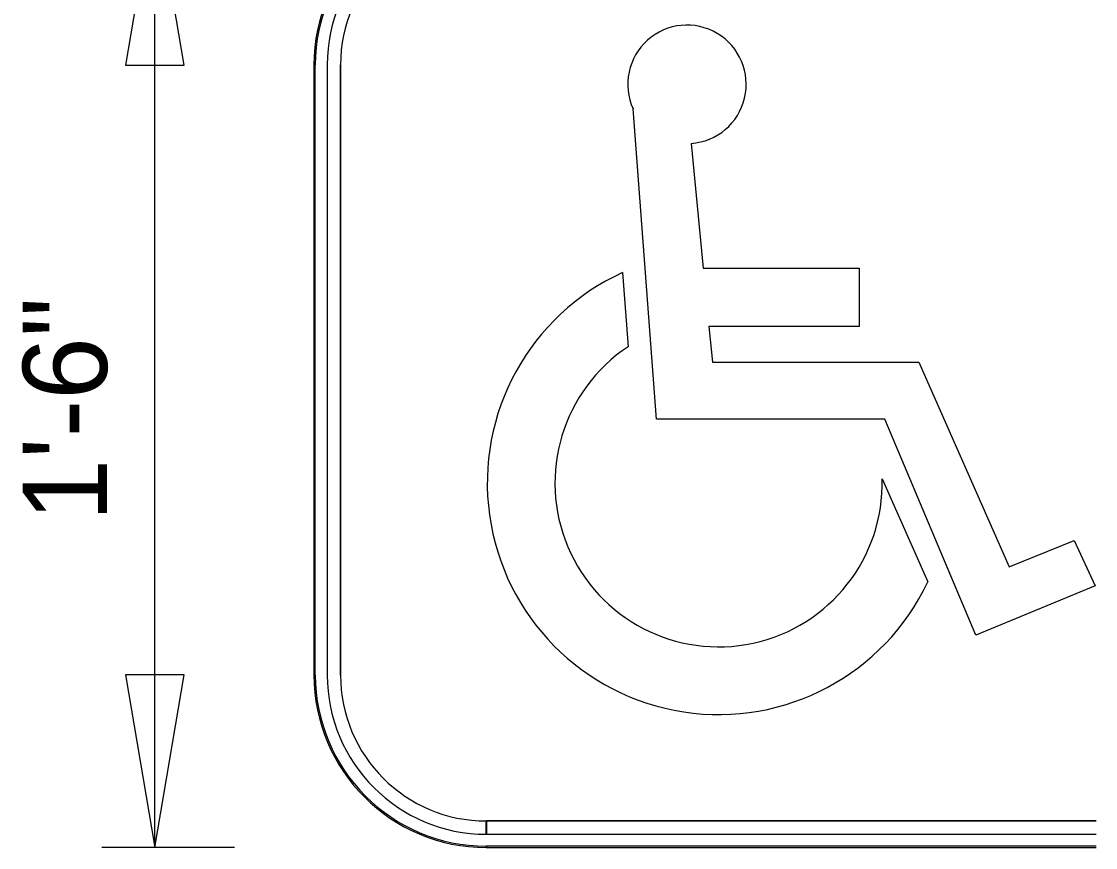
# Model space of a CAD drawing. Extents: x 0 to 770, y 0 to 495.
# Drawn here: x 488.58 to 533.2, y 427.82 to 462.11 of the extents above; entities that cross this region are included whole.
import ezdxf

# ---------------------------------------------------------------- set-up
doc = ezdxf.new("R2010")
doc.units = 0
for name, color, linetype in [('Default', 7, 'Continuous'), ('Dimension', 7, 'Continuous'), ('GSBWFill', 7, 'Continuous'), ('GSColorFill', 7, 'Continuous'), ('GSDims', 7, 'Continuous'), ('GSOutline', 7, 'Continuous'), ('TextStructures', 7, 'Continuous')]:
    doc.layers.add(name, color=color, linetype=linetype)

msp = doc.modelspace()

# ---------------------------------------------------------------- linework, layer by layer
at = {"layer": 'Default'}
for p, q in [((513.555, 451.692), (513.785, 448.609)), ((513.555, 451.692), (513.555, 451.692)), ((513.555, 451.692), (513.785, 448.609)), ((513.555, 451.692), (513.555, 451.692)), ((513.555, 451.692), (513.785, 448.609)), ((513.555, 451.692), (513.555, 451.692)), ((524.338, 443.123), (526.233, 438.843)), ((524.338, 443.123), (526.233, 438.843)), ((524.338, 443.123), (526.233, 438.843))]:
    msp.add_line(p, q, dxfattribs=at)
for points in [[(528.232, 436.629), (524.444, 445.595), (514.968, 445.595), (513.989, 458.487)], [(528.232, 436.629), (524.444, 445.595), (514.968, 445.595), (513.989, 458.487)], [(528.232, 436.629), (524.444, 445.595), (514.968, 445.595), (513.989, 458.487)], [(516.403, 457.05), (516.905, 451.874), (523.379, 451.874), (523.379, 449.449), (517.139, 449.449), (517.287, 447.975), (525.865, 447.975), (529.611, 439.473), (532.312, 440.561), (533.19, 438.681), (528.232, 436.629)], [(516.403, 457.05), (516.905, 451.874), (523.379, 451.874), (523.379, 449.449), (517.139, 449.449), (517.287, 447.975), (525.865, 447.975), (529.611, 439.473), (532.312, 440.561), (533.19, 438.681), (528.232, 436.629)], [(516.403, 457.05), (516.905, 451.874), (523.379, 451.874), (523.379, 449.449), (517.139, 449.449), (517.287, 447.975), (525.865, 447.975), (529.611, 439.473), (532.312, 440.561), (533.19, 438.681), (528.232, 436.629)]]:
    msp.add_lwpolyline(points, dxfattribs=at)
for centre, radius, start, end in [((516.231, 459.505), 2.46, 274.0338, 204.3912), ((516.231, 459.505), 2.46, 274.0338, 204.3912), ((516.231, 459.505), 2.46, 274.0338, 204.3912), ((517.544, 442.946), 9.61, 114.5109, 334.7279), ((517.544, 442.946), 9.61, 114.5109, 334.7279), ((517.544, 442.946), 9.61, 114.5109, 334.7279), ((517.544, 442.946), 6.799, 123.5699, 1.485), ((517.544, 442.946), 6.799, 123.5699, 1.485), ((517.544, 442.946), 6.799, 123.5699, 1.485)]:
    msp.add_arc(centre, radius, start, end, dxfattribs=at)
at = {"layer": 'Dimension'}
for points in [[(494.123, 467.473), (492.908, 460.301), (495.338, 460.301)], [(494.123, 427.815), (495.338, 434.988), (492.908, 434.988)]]:
    msp.add_lwpolyline(points, close=True, dxfattribs=at)
at = {"layer": 'GSBWFill'}
for p, q in [((500.733, 460.313), (500.733, 434.976)), ((501.284, 460.313), (501.284, 434.976)), ((501.835, 434.976), (501.835, 460.313)), ((507.893, 428.366), (507.893, 428.917)), ((533.231, 428.917), (507.899, 428.917)), ((507.899, 428.917), (507.899, 428.366)), ((507.899, 428.366), (533.231, 428.366)), ((507.893, 427.815), (533.231, 427.815))]:
    msp.add_line(p, q, dxfattribs=at)
for centre, radius, start, end in [((507.893, 460.313), 7.161, 90, 180), ((507.893, 460.313), 6.61, 90, 180), ((507.893, 460.313), 6.059, 90, 180), ((507.893, 434.976), 7.161, 180, 270), ((507.893, 434.976), 6.61, 180, 270), ((507.893, 434.976), 6.059, 180, 270)]:
    msp.add_arc(centre, radius, start, end, dxfattribs=at)
at = {"layer": 'GSColorFill'}
for p, q in [((500.733, 460.313), (500.733, 434.976)), ((500.733, 460.313), (500.733, 434.976)), ((500.788, 434.976), (500.788, 460.313)), ((501.284, 460.313), (501.284, 434.976)), ((501.835, 434.976), (501.835, 460.313)), ((507.893, 428.366), (507.893, 428.917)), ((533.231, 428.917), (507.899, 428.917)), ((507.899, 428.917), (507.899, 428.366)), ((507.899, 428.366), (533.231, 428.366)), ((507.893, 427.815), (507.893, 427.87)), ((507.893, 427.815), (533.231, 427.815)), ((533.231, 427.87), (507.894, 427.87)), ((507.894, 427.87), (507.894, 427.815)), ((507.894, 427.815), (533.231, 427.815))]:
    msp.add_line(p, q, dxfattribs=at)
for centre, radius, start, end in [((507.893, 460.313), 7.161, 90, 180), ((507.893, 460.313), 7.161, 90, 180), ((507.893, 460.313), 7.105, 90, 180), ((507.893, 460.313), 6.61, 90, 180), ((507.893, 460.313), 6.059, 90, 180), ((507.893, 434.976), 7.161, 180, 270), ((507.893, 434.976), 7.161, 180, 270), ((507.893, 434.976), 7.105, 180, 270), ((507.893, 434.976), 6.61, 180, 270), ((507.893, 434.976), 6.059, 180, 270)]:
    msp.add_arc(centre, radius, start, end, dxfattribs=at)
at = {"layer": 'GSDims'}
for p, q in [((494.123, 427.815), (494.123, 467.473)), ((497.428, 427.815), (491.92, 427.815))]:
    msp.add_line(p, q, dxfattribs=at)
at = {"layer": 'GSOutline'}
for p, q in [((500.733, 460.313), (500.733, 434.976)), ((501.284, 460.313), (501.284, 434.976)), ((501.835, 460.313), (501.835, 434.976)), ((507.893, 428.917), (533.231, 428.917)), ((507.893, 428.366), (533.231, 428.366)), ((507.893, 427.815), (533.231, 427.815))]:
    msp.add_line(p, q, dxfattribs=at)
for centre, radius, start, end in [((507.893, 460.313), 7.161, 90, 180), ((507.893, 460.313), 6.61, 90, 180), ((507.893, 460.313), 6.059, 90, 180), ((507.893, 434.976), 7.161, 180, 270), ((507.893, 434.976), 6.61, 180, 270), ((507.893, 434.976), 6.059, 180, 270)]:
    msp.add_arc(centre, radius, start, end, dxfattribs=at)

# ---------------------------------------------------------------- texts
at = {"layer": 'TextStructures'}
msp.add_text('1\'-6"', height=3.5, rotation=90, dxfattribs=at).set_placement((492.132, 441.35))

doc.saveas('drawing.dxf')
